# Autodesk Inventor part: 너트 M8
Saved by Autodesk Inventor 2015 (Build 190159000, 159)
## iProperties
Created: 2025-08
Part Number: 너트 M8
Material: 일반
Document SubType Name: Modeling
Designer: USER
Density: 1 g/cm^3
Appearance: 기본값
Author: USER
Author: jhkim
Description: 플랜지붙이 6각 너트 - 일반 스레드
Creation Date: 2025-08-05
Sending System: Autodesk Inventor 2026
Preprocessor: ST-DEVELOPER v20.1
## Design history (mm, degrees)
node "너트 M81"
body "Solid1"
node "기준1"
